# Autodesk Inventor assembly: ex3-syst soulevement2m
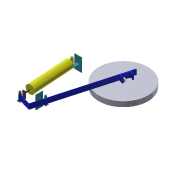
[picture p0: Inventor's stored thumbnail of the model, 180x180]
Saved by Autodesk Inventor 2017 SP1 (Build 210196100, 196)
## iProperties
Part Number: ex3-syst soulevement2m
Material: Générique
Document SubType Name: Assembly
Designer: TJ
Author: TJ
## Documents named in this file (6)
- H:\Consmec\TSsi\02-Cours\02-02-Cinematique\02-02-02-Cinematique graphique\02-02-02-03-Composition des Vitesses\02-02-02-03-02-Exercices compo des Vitesses\02-02-02-03-02-03-Exercice3CompVit\ex3-syst soulevement2m.iam
- H:\Consmec\TSsi\02-Cours\02-02-Cinematique\02-02-02-Cinematique graphique\02-02-02-03-Composition des Vitesses\02-02-02-03-02-Exercices compo des Vitesses\02-02-02-03-02-03-Exercice3CompVit\Pièce5.ipt
- H:\Consmec\TSsi\02-Cours\02-02-Cinematique\02-02-02-Cinematique graphique\02-02-02-03-Composition des Vitesses\02-02-02-03-02-Exercices compo des Vitesses\02-02-02-03-02-03-Exercice3CompVit\Pièce3.ipt
- H:\Consmec\TSsi\02-Cours\02-02-Cinematique\02-02-02-Cinematique graphique\02-02-02-03-Composition des Vitesses\02-02-02-03-02-Exercices compo des Vitesses\02-02-02-03-02-03-Exercice3CompVit\Pièce4.ipt
- H:\Consmec\TSsi\02-Cours\02-02-Cinematique\02-02-02-Cinematique graphique\02-02-02-03-Composition des Vitesses\02-02-02-03-02-Exercices compo des Vitesses\02-02-02-03-02-03-Exercice3CompVit\Pièce2.ipt
- H:\Consmec\TSsi\02-Cours\02-02-Cinematique\02-02-02-Cinematique graphique\02-02-02-03-Composition des Vitesses\02-02-02-03-02-Exercices compo des Vitesses\02-02-02-03-02-03-Exercice3CompVit\Pièce1.ipt
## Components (6 placed, 5 different names)
1. Pièce5:1 — Logement:1, Angle:2, Angle:3
2. Pièce5:2 — Logement:3, Angle:3
3. Pièce3:1 — Logement:1, Placage:1, Angle:1
4. Pièce4:1 — Placage:1, Angle:1, Logement:2, Angle:2
5. Pièce2:1 — Logement:2, Logement:3, Logement:4
6. Pièce1:1 — Logement:4
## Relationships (8: Insert 4, Angle 3, Mate 1)
- Logement:1 [Insert]: Pièce5:1 ↔ Pièce3:1
- Placage:1 [Mate]: Pièce3:1 ↔ Pièce4:1
- Angle:1: Pièce3:1 ↔ Pièce4:1
- Logement:2 [Insert]: Pièce4:1 ↔ Pièce2:1
- Angle:2: Pièce5:1 ↔ Pièce4:1
- Logement:3 [Insert]: Pièce5:2 ↔ Pièce2:1
- Angle:3: Pièce5:1 ↔ Pièce5:2
- Logement:4 [Insert]: Pièce2:1 ↔ Pièce1:1
